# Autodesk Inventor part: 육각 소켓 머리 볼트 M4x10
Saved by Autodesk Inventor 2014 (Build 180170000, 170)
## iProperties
Created: 2024-05
Part Number: 육각 소켓 머리 볼트 M4x10
Material: 일반
Document SubType Name: Modeling
Designer: dg
Density: 1 g/cm^3
Appearance: 기본값
Author: jhkim
Description: 6각머리 태핑 나사
Creation Date: 2024-05-07
Sending System: Autodesk Inventor 2025
Preprocessor: ST-DEVELOPER v20
Author: dg
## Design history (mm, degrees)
node "육각 소켓 머리 볼트 M4x101"
body "Solid1"
node "기준1"
